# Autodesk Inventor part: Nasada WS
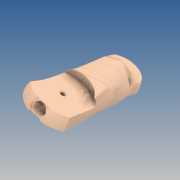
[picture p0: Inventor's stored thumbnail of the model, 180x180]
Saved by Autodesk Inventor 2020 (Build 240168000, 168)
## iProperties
Created: 2019-10
Part Number: Nasada WS
Material: GFRP
Document SubType Name: Modeling
Designer: yello
Density: 1.75 g/cm^3
Appearance: Default
Author: yello
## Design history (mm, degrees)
feature "Nasada WS"
workplane "Work Plane1"
sketch "Sketch2"
  geometry: L1 (3.5, 0)-(3.5, 20); L2 (3.5, 20)-(-3.5, 20); L3 (-3.5, 20)-(-3.5, 0); L4 (-3.5, 0)-(-3.5, -30); L5 (-3.5, -30)-(3.5, -30); L6 (3.5, -30)-(3.5, 0); L7 (0, -30)-(0, 20); A1 r 3.5 centre (0, 0) between (3.5, 0) and (-3.5, 0)
  constraints: 14 end point, 3 perpendicular, 2 midpoint, 2 point on circle, 2 point on line, 2 tangent, 1 centre point, 1 vertical
  dimensions: "d2" = 7 diameter of A1; "d3" = 20 distance of L1.start L1.end; "d4" = 30 distance of L3.end L4.end
revolve "Revolution1" sketch "Sketch2" stored, may be unused: angle "d5" = 90 deg
workplane "Work Plane3"
sketch "Sketch10"
  geometry: C1 r 95.129 at (-22.981, -21.642); 1 further point
  constraints: 1 centre point
workplane "Work Plane5"
sketch "Sketch14"
  geometry: C1 r 4.25 at (0, 0); A1 r 3.5 centre (0, 0) between (3.274, -1.237) and (3.274, -1.237) reference
  constraints: 1 centre point, 1 coincident
  dimensions: "d16" = 8.5 diameter of C1
extrude "Extrusion4" cut sketch "Sketch14" stored distance "d17" = 2; taper "d18" = 0 deg
workplane "Work Plane6"
sketch "Sketch15"
  geometry: L1 (0, 1.5)-(0, -1.5); A1 r 1.5 centre (0, 0) between (0, 1.5) and (0, -1.5); 1 further point
  constraints: 2 end point, 2 point on circle, 1 centre point, 1 vertical
  dimensions: "d21" = 3 diameter of A1
revolve "Revolution2" sketch "Sketch15" stored, may be unused: angle "d22" = 90 deg
mirror "Mirror1"
workaxis "Work Axis1"
fillet "Fillet1" dims "d23" = 1
workplane "Work Plane8"
sketch "Sketch17"
  geometry: L1 (0, 0)-(7, 0) reference; L2 (3.5, 0)-(3.5, 3.75) reference; L3 (3.5, 3.75)-(3.5, 12); L4 (2.5, 3.75)-(2.5, 12); L5 (4.5, 12)-(4.5, 3.75); A1 r 1 centre (3.5, 3.75) between (2.5, 3.75) and (4.5, 3.75); A2 r 1 centre (3.5, 12) between (4.5, 12) and (2.5, 12); 1 further point
  constraints: 12 end point, 4 point on circle, 3 vertical, 2 centre point, 2 midpoint, 1 coincident, 1 equal radius, 1 horizontal, 1 other
  dimensions: "d28" = 8.25 distance of L3.start L3.end; "d31" = 1 radius of A2 (derived); "d34" = 1 radius of A1
extrude "Extrusion5" cut sketch "Sketch17" distance "d29" = 15; taper "d30" = 0 deg
sketch "Sketch18"
  geometry: C1 r 5 at (0, 0); 1 further point
  constraints: 1 centre point
  dimensions: "d36" = 10 diameter of C1
extrude "Extrusion6" cut sketch "Sketch18" distance "d37" = 8; taper "d38" = 0 deg
body "Solid1"
other parameters: "d15" = 45, "d19" = 3.5, "d25" = -15
